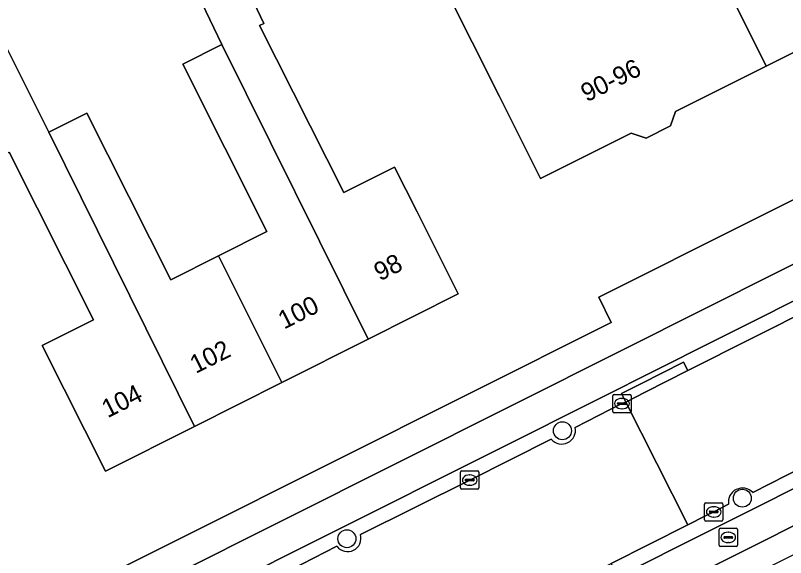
# Model space of a CAD drawing. Extents: x 157320 to 158835, y 386650 to 388491.
# Drawn here: x 157600.03 to 157641.97, y 387666.34 to 387695.88 of the extents above; entities that cross this region are included whole.
import ezdxf

# ---------------------------------------------------------------- set-up
doc = ezdxf.new("R2010")
doc.units = 0
for name, color, linetype in [('IMGEO_Berm_open', 7, 'Continuous'), ('IMGEO_Boom', 7, 'Continuous'), ('IMGEO_Brandkraan', 7, 'Continuous'), ('IMGEO_Erf', 7, 'Continuous'), ('IMGEO_Fietspad_open', 7, 'Continuous'), ('IMGEO_Kolk', 7, 'Continuous'), ('IMGEO_Pand', 7, 'Continuous'), ('IMGEO_Pand_nummerreeks', 7, 'Continuous'), ('IMGEO_Rijbaan_lokaal_open', 7, 'Continuous'), ('IMGEO_Voetpad_open', 7, 'Continuous')]:
    doc.layers.add(name, color=color, linetype=linetype)

msp = doc.modelspace()

# ---------------------------------------------------------------- linework, layer by layer
at = {"layer": 'IMGEO_Berm_open'}
for points in [[(157689.313, 387702.997), (157689.087, 387703.419), (157688.948, 387703.712), (157688.853, 387703.664), (157658.704, 387688.508), (157633.965, 387676.076), (157632.808, 387675.494), (157602.899, 387660.494), (157587.041, 387652.538), (157567.394, 387642.71), (157567.399, 387642.417)], [(157586.607, 387643), (157582.123, 387640.749), (157577.438, 387638.409), (157574.054, 387636.702), (157569.341, 387634.325), (157569.697, 387633.623), (157597.83, 387647.706), (157616.763, 387657.23), (157637.927, 387667.851), (157666.428, 387682.154)], [(157630.518, 387673.434), (157633.06, 387674.73), (157633.267, 387674.819), (157633.035, 387675.276), (157634.094, 387675.811), (157636.413, 387676.983), (157636.639, 387676.533), (157643.624, 387680.048)], [(157652.428, 387676.043), (157643.892, 387671.775), (157640.178, 387669.894)], [(157618.813, 387667.595), (157624.77, 387670.564), (157629.208, 387672.795)], [(157638.861, 387669.25), (157638.058, 387668.836), (157637.609, 387668.61), (157636.643, 387668.123), (157632.47, 387666.019), (157632.672, 387665.568), (157631.35, 387664.896), (157631.116, 387665.348), (157626.402, 387662.945), (157626.611, 387662.52), (157620.505, 387659.442), (157620.273, 387659.907), (157616.477, 387658.002), (157614.728, 387657.12)], [(157602.642, 387659.467), (157603.41, 387659.846), (157603.186, 387660.289), (157609.957, 387663.681), (157610.198, 387663.236), (157613.09, 387664.687), (157617.539, 387666.961)]]:
    msp.add_lwpolyline(points, dxfattribs=at)
msp.add_lwpolyline([(157636.639, 387676.533), (157636.413, 387676.983), (157634.094, 387675.811), (157633.035, 387675.276), (157633.267, 387674.819), (157634.318, 387675.353)], close=True, dxfattribs=at)
for centre, radius, start, end in [((157629.781, 387673.282), 0.752, 220.3572, 11.6477), ((157639.622, 387669.362), 0.769, 43.7526, 188.3638), ((157618.12, 387667.391), 0.723, 216.4996, 16.4144)]:
    msp.add_arc(centre, radius, start, end, dxfattribs=at)
at = {"layer": 'IMGEO_Boom'}
for centre in [(157629.818, 387673.254), (157639.614, 387669.579), (157618.078, 387667.372)]:
    msp.add_circle(centre, 0.489, dxfattribs=at)
at = {"layer": 'IMGEO_Brandkraan'}
for p, q in [((157638.347, 387667.015), (157638.347, 387667.867)), ((157638.422, 387667.941), (157639.274, 387667.941)), ((157639.348, 387667.867), (157639.348, 387667.015)), ((157638.606, 387667.435), (157638.606, 387667.447)), ((157638.649, 387667.484), (157639.047, 387667.484)), ((157638.835, 387667.721), (157638.86, 387667.721)), ((157639.09, 387667.447), (157639.09, 387667.435)), ((157639.044, 387667.398), (157638.646, 387667.398)), ((157638.858, 387667.161), (157638.833, 387667.161)), ((157639.274, 387666.941), (157638.422, 387666.941))]:
    msp.add_line(p, q, dxfattribs=at)
for points in [[(157638.347, 387667.015), (157638.347, 387667.867)], [(157638.422, 387667.941), (157639.274, 387667.941)], [(157639.348, 387667.867), (157639.348, 387667.015)], [(157639.274, 387666.941), (157638.422, 387666.941)]]:
    msp.add_lwpolyline(points, dxfattribs=at)
for centre, radius, start, end in [((157638.424, 387667.865), 0.0765, 91.552, 178.448), ((157638.424, 387667.865), 0.0765, 91.552, 178.448), ((157639.272, 387667.865), 0.0765, 1.552, 88.448), ((157639.272, 387667.865), 0.0765, 1.552, 88.448), ((157638.646, 387667.444), 0.0403, 85.8775, 175.7526), ((157638.643, 387667.434), 0.0366, 178.938, 274.7102), ((157639.047, 387667.441), 0.043, 264.8664, 352.4533), ((157639.051, 387667.446), 0.0386, 1.7309, 96.639), ((157638.424, 387667.017), 0.0765, 181.552, 268.448), ((157638.424, 387667.017), 0.0765, 181.552, 268.448), ((157639.272, 387667.017), 0.0765, 271.552, 358.448), ((157639.272, 387667.017), 0.0765, 271.552, 358.448)]:
    msp.add_arc(centre, radius, start, end, dxfattribs=at)
for centre, major_axis, ratio, start_param, end_param in [((157638.834, 387667.441), (-0.387, 0.002), 0.722429, 4.712389, 7.853982), ((157638.859, 387667.441), (-0.39, 0.002), 0.717154, 1.570796, 4.712389)]:
    msp.add_ellipse(centre, major_axis=major_axis, ratio=ratio, start_param=start_param, end_param=end_param, dxfattribs=at)
at = {"layer": 'IMGEO_Erf'}
for points in [[(157645.665, 387695.496), (157640.914, 387693.119), (157635.973, 387690.647), (157635.711, 387689.86), (157634.372, 387689.191), (157633.563, 387689.46), (157628.623, 387686.989), (157626.388, 387691.457), (157623.417, 387697.395), (157623.781, 387697.577), (157625.918, 387698.646), (157626.31, 387697.861), (157636.094, 387702.756), (157635.701, 387703.541), (157637.974, 387704.677), (157638.366, 387703.893), (157645.639, 387707.532)], [(157610.953, 387700.898), (157613.563, 387695.433), (157613.326, 387695.332), (157617.904, 387686.222), (157620.672, 387687.614), (157621.897, 387685.176), (157624.143, 387680.708), (157619.246, 387678.247), (157614.535, 387675.879), (157609.78, 387673.489), (157604.927, 387671.05), (157602.682, 387675.518), (157601.484, 387677.901), (157604.271, 387679.301), (157599.682, 387688.432)], [(157599.104, 387694.957), (157601.849, 387689.515), (157603.917, 387690.555), (157608.484, 387681.469), (157611.093, 387682.781), (157613.72, 387684.101), (157609.135, 387693.225), (157611.261, 387694.294), (157608.635, 387699.791)], [(157564.366, 387646.663), (157577.637, 387653.335), (157578.314, 387651.995), (157579.644, 387652.658), (157579.588, 387652.785), (157585.532, 387655.755), (157585.592, 387655.625), (157601.748, 387663.749), (157632.467, 387679.145), (157631.791, 387680.53), (157656.318, 387692.814)]]:
    msp.add_lwpolyline(points, dxfattribs=at)
at = {"layer": 'IMGEO_Fietspad_open'}
for points in [[(157632.808, 387675.494), (157633.965, 387676.076), (157658.704, 387688.508), (157688.853, 387703.664), (157688.948, 387703.712), (157688.179, 387705.325), (157687.79, 387705.127), (157658.586, 387690.459), (157633.171, 387677.702), (157602.223, 387662.168), (157586.268, 387654.276), (157565.674, 387643.795)], [(157567.399, 387642.417), (157567.394, 387642.71), (157587.041, 387652.538), (157602.899, 387660.494), (157632.808, 387675.494)]]:
    msp.add_lwpolyline(points, dxfattribs=at)
msp.add_lwpolyline([(157638.747, 387666.244), (157666.647, 387680.247), (157675.661, 387684.73), (157674.827, 387686.387), (157672.423, 387685.176), (157666.428, 387682.154), (157637.927, 387667.851), (157616.763, 387657.23), (157597.83, 387647.706), (157569.697, 387633.623), (157569.232, 387631.358), (157569.945, 387631.713)], close=True, dxfattribs=at)
at = {"layer": 'IMGEO_Kolk'}
for p, q in [((157632.559, 387674.306), (157632.559, 387675.158)), ((157632.634, 387675.232), (157633.486, 387675.232)), ((157633.047, 387675.012), (157633.072, 387675.012)), ((157633.56, 387675.158), (157633.56, 387674.306)), ((157632.818, 387674.726), (157632.818, 387674.738)), ((157633.256, 387674.689), (157632.858, 387674.689)), ((157632.861, 387674.775), (157633.259, 387674.775)), ((157633.302, 387674.738), (157633.302, 387674.726)), ((157633.486, 387674.232), (157632.634, 387674.232)), ((157633.07, 387674.452), (157633.045, 387674.452)), ((157624.269, 387670.139), (157624.269, 387670.991)), ((157624.344, 387671.065), (157625.196, 387671.065)), ((157624.757, 387670.845), (157624.782, 387670.845)), ((157625.27, 387670.991), (157625.27, 387670.139)), ((157624.528, 387670.559), (157624.528, 387670.571)), ((157624.966, 387670.522), (157624.568, 387670.522)), ((157624.571, 387670.608), (157624.969, 387670.608)), ((157625.012, 387670.571), (157625.012, 387670.559)), ((157625.196, 387670.065), (157624.344, 387670.065)), ((157624.78, 387670.285), (157624.755, 387670.285)), ((157637.558, 387668.408), (157637.558, 387669.26)), ((157637.633, 387669.334), (157638.485, 387669.334)), ((157638.046, 387669.114), (157638.071, 387669.114)), ((157638.559, 387669.26), (157638.559, 387668.408)), ((157637.817, 387668.828), (157637.817, 387668.84)), ((157638.255, 387668.791), (157637.857, 387668.791)), ((157637.86, 387668.877), (157638.258, 387668.877)), ((157638.301, 387668.84), (157638.301, 387668.828)), ((157638.485, 387668.334), (157637.633, 387668.334)), ((157638.069, 387668.554), (157638.044, 387668.554))]:
    msp.add_line(p, q, dxfattribs=at)
for points in [[(157632.559, 387674.306), (157632.559, 387675.158)], [(157632.634, 387675.232), (157633.486, 387675.232)], [(157633.56, 387675.158), (157633.56, 387674.306)], [(157633.486, 387674.232), (157632.634, 387674.232)], [(157624.269, 387670.139), (157624.269, 387670.991)], [(157624.344, 387671.065), (157625.196, 387671.065)], [(157625.27, 387670.991), (157625.27, 387670.139)], [(157625.196, 387670.065), (157624.344, 387670.065)], [(157637.558, 387668.408), (157637.558, 387669.26)], [(157637.633, 387669.334), (157638.485, 387669.334)], [(157638.559, 387669.26), (157638.559, 387668.408)], [(157638.485, 387668.334), (157637.633, 387668.334)]]:
    msp.add_lwpolyline(points, dxfattribs=at)
for centre, radius, start, end in [((157632.636, 387675.156), 0.0765, 91.552, 178.448), ((157632.636, 387675.156), 0.0765, 91.552, 178.448), ((157633.484, 387675.156), 0.0765, 1.552, 88.448), ((157633.484, 387675.156), 0.0765, 1.552, 88.448), ((157632.858, 387674.735), 0.0403, 85.8775, 175.7526), ((157632.855, 387674.725), 0.0366, 178.938, 274.7102), ((157633.259, 387674.732), 0.043, 264.8664, 352.4533), ((157633.263, 387674.737), 0.0386, 1.7309, 96.639), ((157632.636, 387674.308), 0.0765, 181.552, 268.448), ((157632.636, 387674.308), 0.0765, 181.552, 268.448), ((157633.484, 387674.308), 0.0765, 271.552, 358.448), ((157633.484, 387674.308), 0.0765, 271.552, 358.448), ((157624.346, 387670.989), 0.0765, 91.552, 178.448), ((157624.346, 387670.989), 0.0765, 91.552, 178.448), ((157625.194, 387670.989), 0.0765, 1.552, 88.448), ((157625.194, 387670.989), 0.0765, 1.552, 88.448), ((157624.568, 387670.568), 0.0403, 85.8775, 175.7526), ((157624.565, 387670.558), 0.0366, 178.938, 274.7102), ((157624.969, 387670.565), 0.043, 264.8664, 352.4533), ((157624.973, 387670.57), 0.0386, 1.7309, 96.639), ((157624.346, 387670.141), 0.0765, 181.552, 268.448), ((157624.346, 387670.141), 0.0765, 181.552, 268.448), ((157625.194, 387670.141), 0.0765, 271.552, 358.448), ((157625.194, 387670.141), 0.0765, 271.552, 358.448), ((157637.635, 387669.258), 0.0765, 91.552, 178.448), ((157637.635, 387669.258), 0.0765, 91.552, 178.448), ((157638.483, 387669.258), 0.0765, 1.552, 88.448), ((157638.483, 387669.258), 0.0765, 1.552, 88.448), ((157637.857, 387668.837), 0.0403, 85.8775, 175.7526), ((157637.854, 387668.827), 0.0366, 178.938, 274.7102), ((157638.258, 387668.834), 0.043, 264.8664, 352.4533), ((157638.262, 387668.839), 0.0386, 1.7309, 96.639), ((157637.635, 387668.41), 0.0765, 181.552, 268.448), ((157637.635, 387668.41), 0.0765, 181.552, 268.448), ((157638.483, 387668.41), 0.0765, 271.552, 358.448), ((157638.483, 387668.41), 0.0765, 271.552, 358.448)]:
    msp.add_arc(centre, radius, start, end, dxfattribs=at)
for centre, major_axis, ratio, start_param, end_param in [((157633.046, 387674.732), (-0.387, 0.002), 0.722429, 4.712389, 7.853982), ((157633.071, 387674.732), (-0.39, 0.002), 0.717154, 1.570796, 4.712389), ((157624.756, 387670.565), (-0.387, 0.002), 0.722429, 4.712389, 7.853982), ((157624.781, 387670.565), (-0.39, 0.002), 0.717154, 1.570796, 4.712389), ((157638.045, 387668.834), (-0.387, 0.002), 0.722429, 4.712389, 7.853982), ((157638.07, 387668.834), (-0.39, 0.002), 0.717154, 1.570796, 4.712389)]:
    msp.add_ellipse(centre, major_axis=major_axis, ratio=ratio, start_param=start_param, end_param=end_param, dxfattribs=at)
at = {"layer": 'IMGEO_Pand'}
for points in [[(157650.87, 387703.697), (157647.884, 387709.666), (157647.616, 387709.531), (157645.247, 387708.316), (157645.639, 387707.532), (157638.366, 387703.893), (157637.974, 387704.677), (157635.701, 387703.541), (157636.094, 387702.756), (157639.655, 387695.638), (157640.914, 387693.119), (157645.665, 387695.496), (157646.499, 387695.219), (157647.75, 387695.844), (157648.03, 387696.685), (157653.107, 387699.225)], [(157639.655, 387695.638), (157636.094, 387702.756), (157626.31, 387697.861), (157625.918, 387698.646), (157623.781, 387697.577), (157623.417, 387697.395), (157626.388, 387691.457), (157628.623, 387686.989), (157633.563, 387689.46), (157634.372, 387689.191), (157635.711, 387689.86), (157635.973, 387690.647), (157640.914, 387693.119)], [(157613.326, 387695.332), (157613.563, 387695.433), (157610.953, 387700.898), (157608.635, 387699.791), (157611.261, 387694.294), (157619.246, 387678.247), (157624.143, 387680.708), (157621.897, 387685.176), (157620.672, 387687.614), (157617.904, 387686.222)], [(157609.78, 387673.489), (157601.849, 387689.515), (157599.104, 387694.957), (157595.569, 387693.18), (157598.303, 387687.739), (157599.682, 387688.432), (157604.271, 387679.301), (157601.484, 387677.901), (157602.682, 387675.518), (157604.927, 387671.05)], [(157611.093, 387682.781), (157614.535, 387675.879), (157619.246, 387678.247), (157611.261, 387694.294), (157609.135, 387693.225), (157613.72, 387684.101)], [(157611.093, 387682.781), (157608.484, 387681.469), (157603.917, 387690.555), (157601.849, 387689.515), (157609.78, 387673.489), (157614.535, 387675.879)]]:
    msp.add_lwpolyline(points, close=True, dxfattribs=at)
at = {"layer": 'IMGEO_Rijbaan_lokaal_open'}
for points in [[(157643.624, 387680.048), (157636.639, 387676.533), (157634.318, 387675.353), (157633.267, 387674.819), (157636.643, 387668.123), (157637.609, 387668.61), (157638.058, 387668.836), (157638.861, 387669.25)], [(157640.178, 387669.894), (157643.892, 387671.775), (157652.428, 387676.043)], [(157614.728, 387657.12), (157616.477, 387658.002), (157620.273, 387659.907), (157626.402, 387662.945), (157631.116, 387665.348), (157632.47, 387666.019), (157636.643, 387668.123), (157633.267, 387674.819), (157633.06, 387674.73), (157630.518, 387673.434)], [(157629.208, 387672.795), (157624.77, 387670.564), (157618.813, 387667.595)], [(157617.539, 387666.961), (157613.09, 387664.687), (157610.198, 387663.236), (157603.41, 387659.846), (157602.642, 387659.467)]]:
    msp.add_lwpolyline(points, dxfattribs=at)
for centre, radius, start, end in [((157629.781, 387673.282), 0.752, 220.3572, 11.6477), ((157639.622, 387669.362), 0.769, 43.7526, 188.3638), ((157618.12, 387667.391), 0.723, 216.4996, 16.4144)]:
    msp.add_arc(centre, radius, start, end, dxfattribs=at)
at = {"layer": 'IMGEO_Voetpad_open'}
for points in [[(157687.79, 387705.127), (157688.179, 387705.325), (157687.478, 387706.796), (157682.695, 387704.388), (157682.023, 387705.714), (157657.627, 387693.47), (157657.128, 387693.22), (157656.318, 387692.814), (157631.791, 387680.53), (157632.467, 387679.145), (157601.748, 387663.749), (157585.592, 387655.625), (157585.532, 387655.755), (157579.588, 387652.785), (157579.644, 387652.658), (157578.314, 387651.995), (157577.637, 387653.335), (157564.366, 387646.663), (157560.83, 387644.885), (157561.724, 387644.197), (157562.048, 387644.013)], [(157565.674, 387643.795), (157586.268, 387654.276), (157602.223, 387662.168), (157633.171, 387677.702), (157658.586, 387690.459), (157687.79, 387705.127)], [(157675.661, 387684.73), (157666.647, 387680.247), (157638.747, 387666.244), (157569.945, 387631.713), (157569.232, 387631.358), (157568.84, 387629.444), (157570.984, 387630.438), (157617.129, 387653.586), (157634.079, 387662.144), (157633.991, 387662.311), (157639.374, 387664.995), (157665.792, 387678.165), (157676.207, 387683.552)]]:
    msp.add_lwpolyline(points, dxfattribs=at)

# ---------------------------------------------------------------- texts
at = {"layer": 'IMGEO_Pand_nummerreeks'}
for s, rotation, p in [('90-96', 26.6196, (157631.139, 387691.135)), ('98', 26.6826, (157619.874, 387681.383)), ('100', 26.6842, (157614.659, 387678.761)), ('102', 26.6842, (157609.85, 387676.344)), ('104', 26.6842, (157605.048, 387673.93))]:
    msp.add_text(s, height=1, rotation=rotation, dxfattribs=at).set_placement(p)

doc.saveas('drawing.dxf')
